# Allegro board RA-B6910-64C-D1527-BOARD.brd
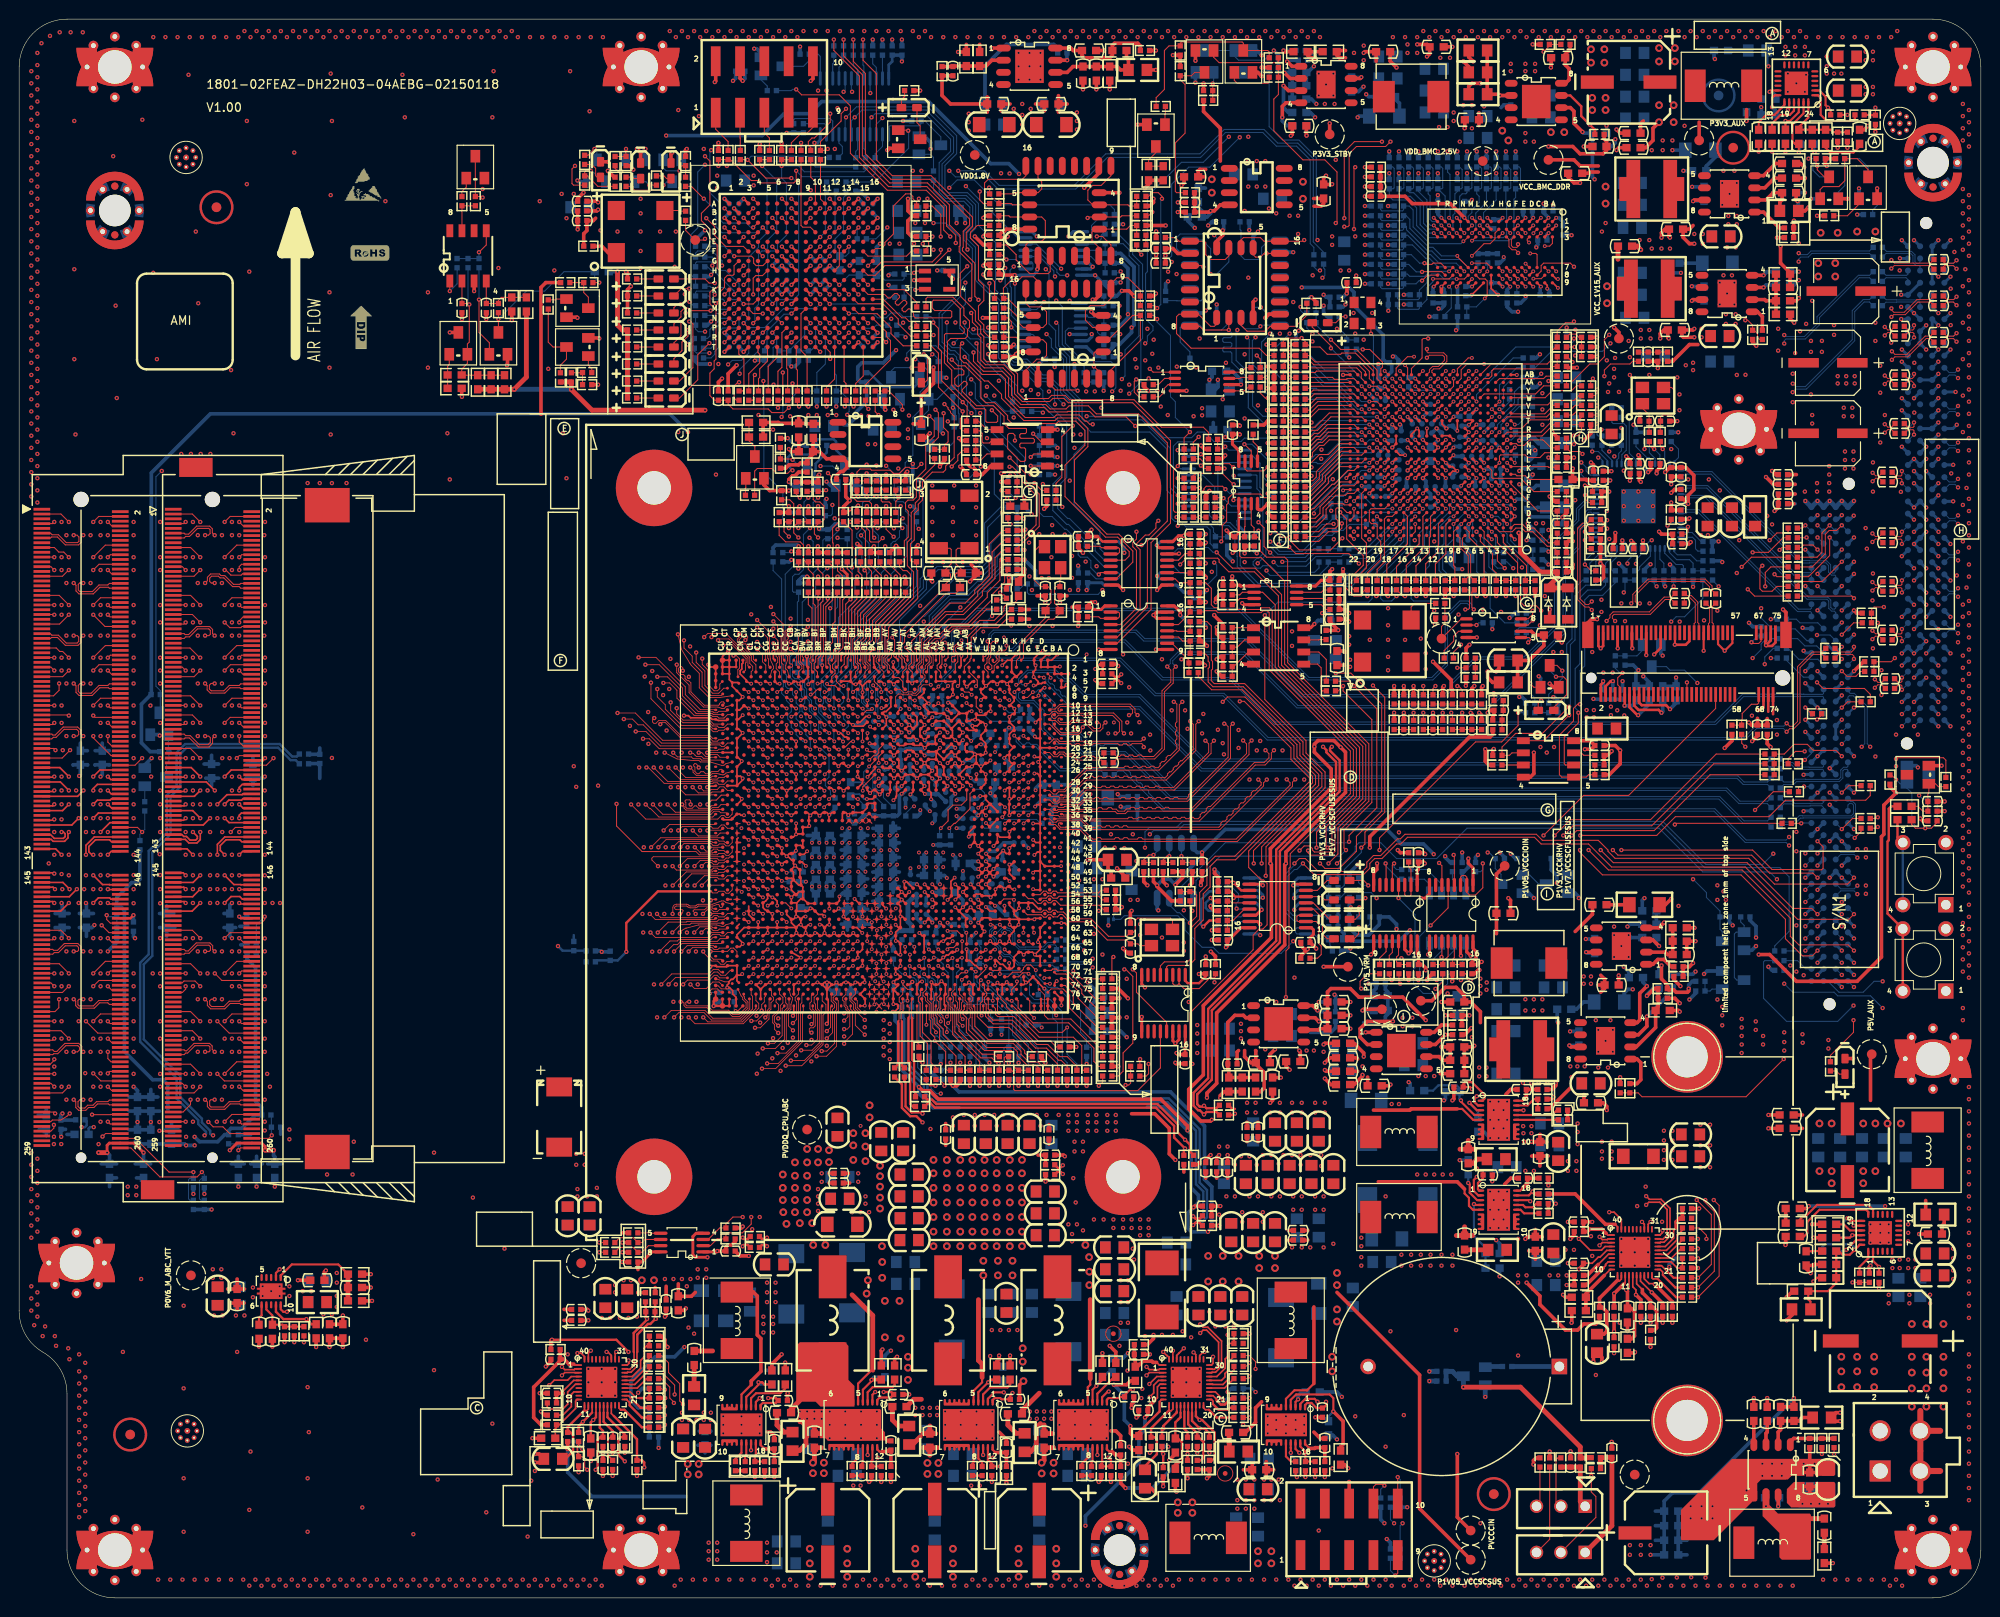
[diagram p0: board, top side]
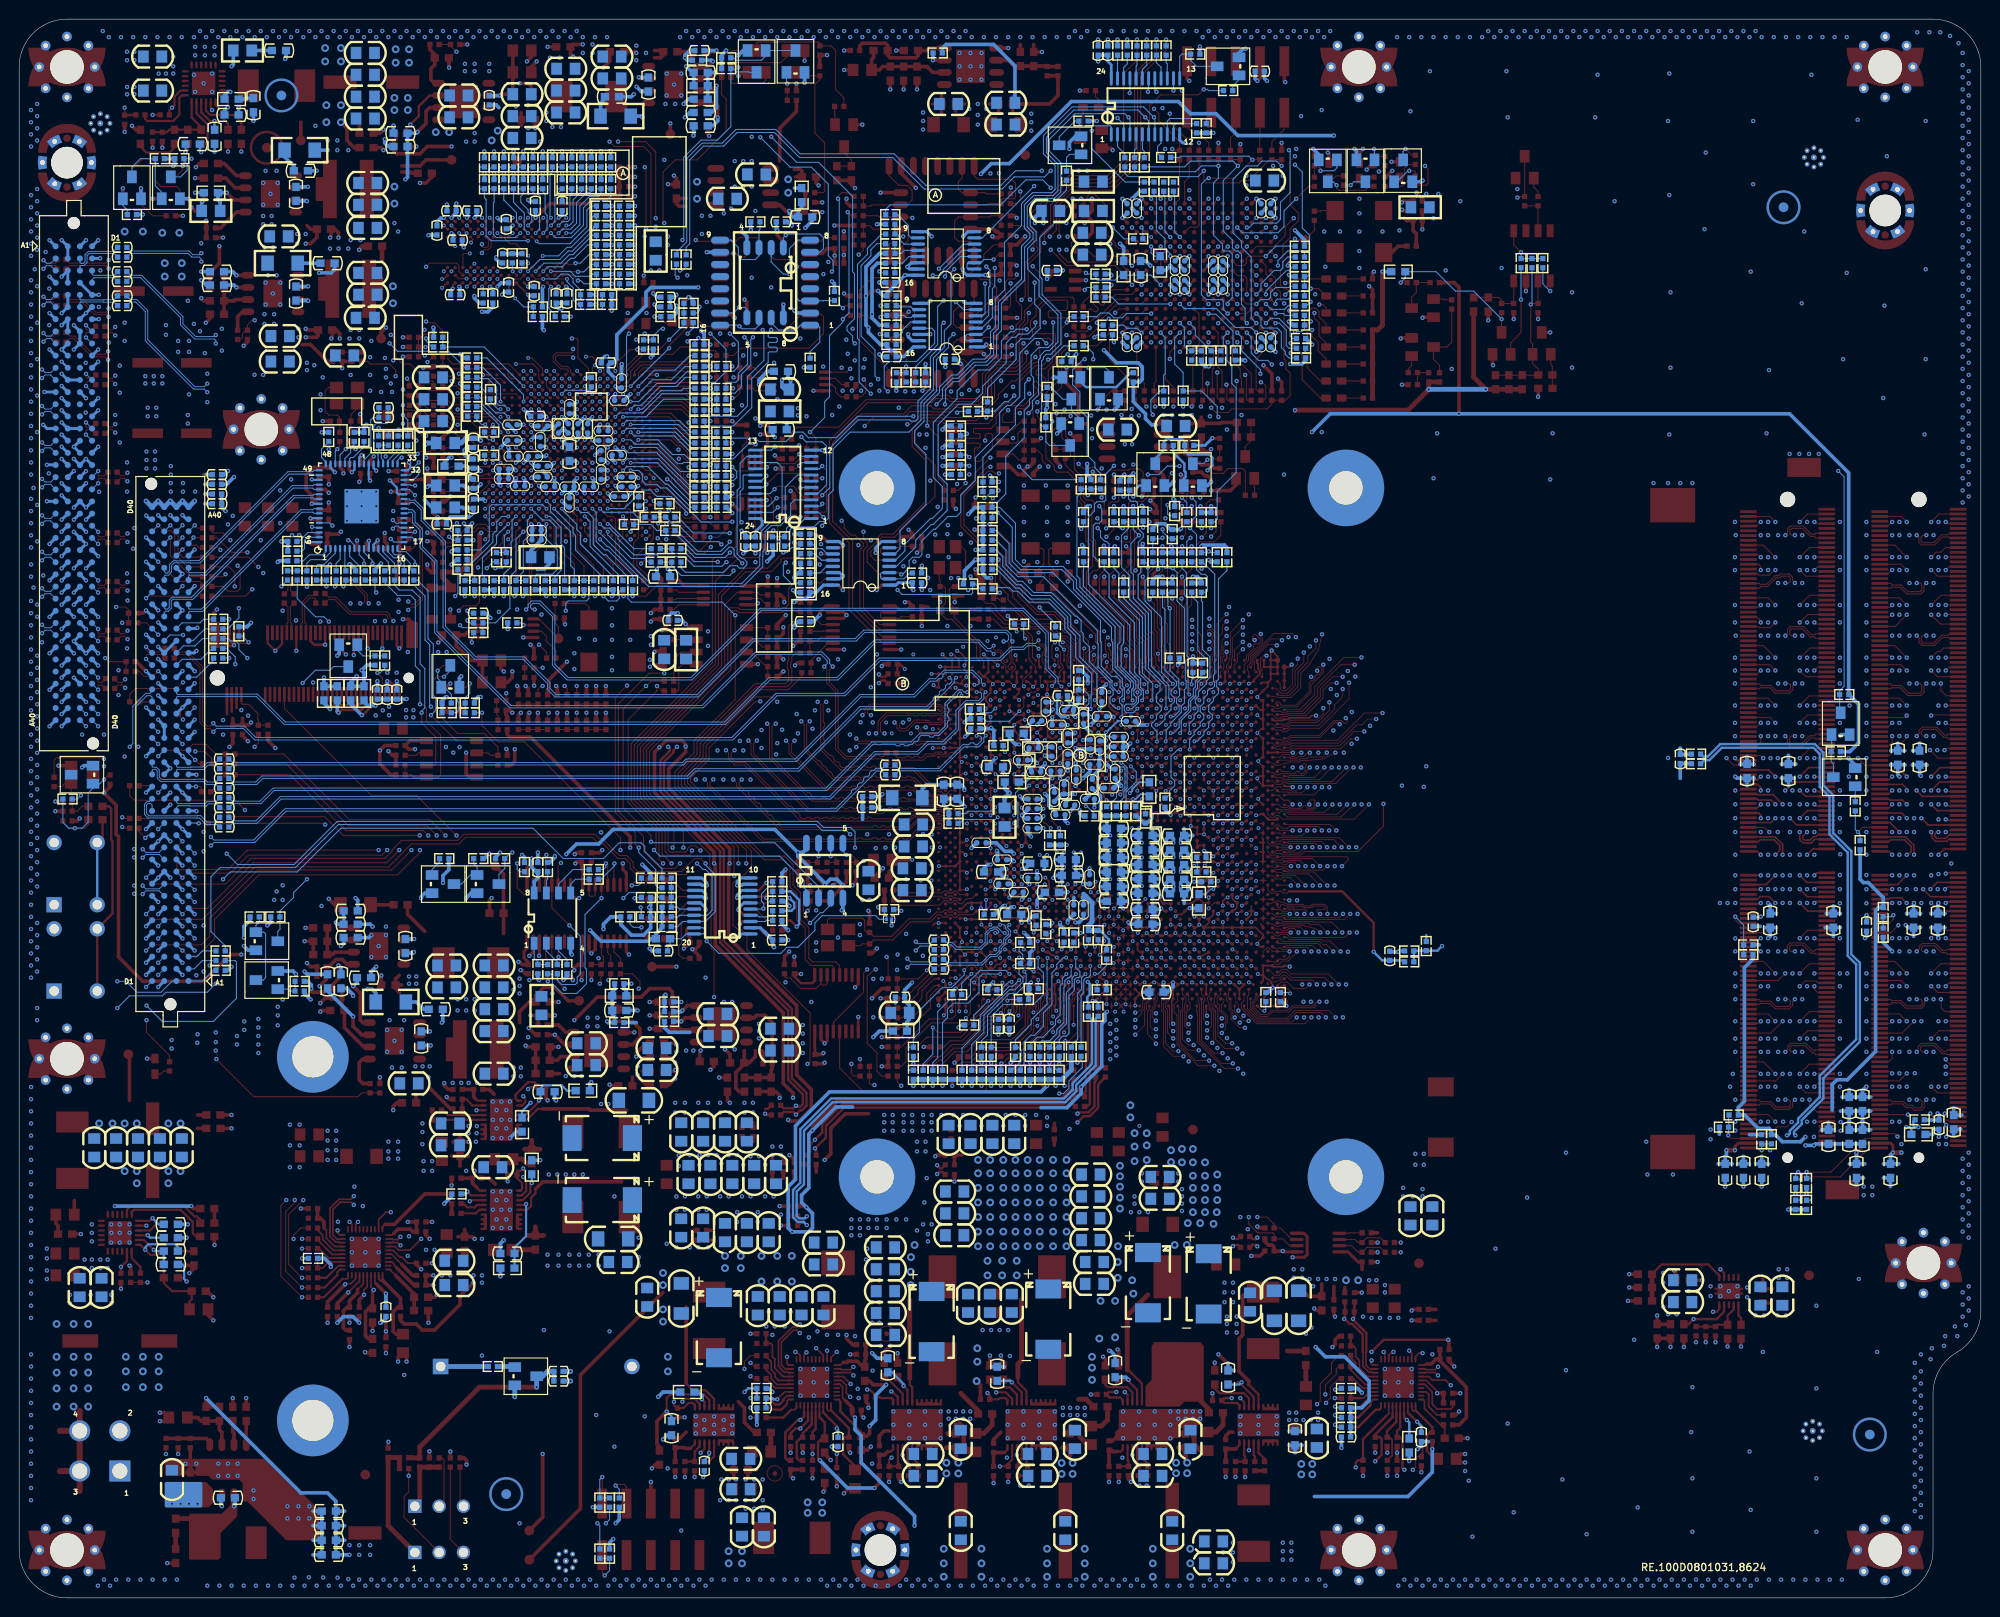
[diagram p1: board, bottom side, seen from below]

Outline 205 x 165 mm; copper layers: TOP, GND1, SIG1, GND2, SIG2, POWER1, POWER2, SIG3, GND3, SIG4, GND4, BOTTOM. Coordinates in mm from the lower left corner of the outline.
Outline path: 0,160 arc(1.46,163.54) 5,165 200,165 arc(203.54,163.54) 205,160 205,5 arc(203.54,1.46) 200,0 10,0 arc(6.46,1.46) 5,5 5,21.34 arc(4.33,23.84) 2.5,25.67 arc(0.67,27.5) 0,30 0,160

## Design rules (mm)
net group 24C02_WP: nets 24C02_WP N11777003
net group 1000M_MDI0: nets 1000M_MDI0N 1000M_MDI0P
net group 1000M_MDI1: nets 1000M_MDI1N 1000M_MDI1P
net group 1000M_MDI2: nets 1000M_MDI2N 1000M_MDI2P
net group 1000M_MDI3: nets 1000M_MDI3N 1000M_MDI3P
net group ADCAV33: nets N51572 N51617
net group ASKIP_VCCGBE: nets ASKIP_VCCGBE EN/FCCM_VCCSCSUS_16997268
net group ASKIP_VCCIN: nets ASKIP_VCCIN N16937550
net group ASKIP_VDDQ: nets ASKIP_VDDQ N17031638
net group BMC_9641_INT#: nets BMC_9641_INT# N12431544
net group BMC_ADC0: nets BMC_ADC0 N12560407
net group BMC_ADC1: nets BMC_ADC1 N12560503
net group BMC_ADC2: nets BMC_ADC2 N12560842
net group BMC_ADC3: nets BMC_ADC3 N12560934
net group BMC_ADC4: nets BMC_ADC4 N12558953
net group BMC_ADC5: nets BMC_ADC5 N12556062
net group BMC_ADC6: nets BMC_ADC6 N12556533
net group BMC_ADC7: nets BMC_ADC7 N12557485
net group BMC_ADC8: nets BMC_ADC8 N12558669
net group BMC_ADC9: nets BMC_ADC9 N12558773
net group BMC_ALERT_N: nets BMC_ALERT_N N187134720
net group BMC_EXTRST_N: nets BMC_EXTRST_N N18404132
net group BMC_GPIO_RS0: nets BMC_GPIO_RS0 N12446840
net group BMC_I2C_RST#: nets BMC_I2C_RST# N12451802
net group BMC_I2C_SCL: nets BMC_I2C_SCL N18655553
net group BMC_SCL: nets BMC_SCL N18713379
net group BMC_SDA: nets BMC_SDA N18713382
net group BMC_SRST_N: nets BMC_SRST_N N18404109
net group BMCO_UART_RXD1: nets BMC_UART_RXD1 BMCO_UART_RXD1
net group BMCO_UART_TXD1: nets BMC_UART_TXD1 BMCO_UART_TXD1
net group BROAD_RST#: nets BROAD_RST# N12446425
net group BSKIP_P1V05_PCH: nets BSKIP_P1V05_PCH EN/FCCM_P1V05_PCH
net group BSKIP_P2V5_VPP: nets BSKIP_P2V5_VPP EN/FCCM_VCCSCSUS_17116599
net group BSKIP_VCCSCSUS: nets BSKIP_VCCSCSUS EN/FCCM_VCCSCSUS
net group CATERR_N: nets CATERR_N CATERR_N_GTL
net group CIE_TX_0: nets PCIE_TX_N0 PCIE_TX_P0
net group CIE_TX_1: nets PCIE_TX_N1 PCIE_TX_P1
net group CIE_TX_2: nets PCIE_TX_N2 PCIE_TX_P2
net group CIE_TX_3: nets PCIE_TX_N3 PCIE_TX_P3
net group CLK_33M: nets CLK_33M N1731399
net group CLK_33M_LOOPBACK: nets CLK_33M_LOOPBACK N1731571
net group CLKOUT_CIE_D0: nets CLKOUT_PCIE_DN0 CLKOUT_PCIE_DP0
net group CLKOUT_CIE_D1: nets CLKOUT_PCIE_DN1 CLKOUT_PCIE_DP1
net group CLKOUT_CIE_D2: nets CLKOUT_PCIE_DN2 CLKOUT_PCIE_DP2
net group CLKOUT_CIE_D3: nets CLKOUT_PCIE_DN3 CLKOUT_PCIE_DP3
net group CLKOUT_CIE_D4: nets CLKOUT_PCIE_DN4 CLKOUT_PCIE_DP4
net group CLKOUT_CIE_D5: nets CLKOUT_PCIE_DN5 CLKOUT_PCIE_DP5
net group CLKOUT_CIE_D6: nets CLKOUT_PCIE_DN6 CLKOUT_PCIE_DP6
net group CLKOUT_CIE_D7: nets CLKOUT_PCIE_DN7 CLKOUT_PCIE_DP7
net group CPLD_25M_CLK: nets CPLD_25M_CLK N17832341
net group CPLD_CLK_50M: nets CPLD_CLK_50M N12564408
net group CPLD_ERR0_N: nets CPLD_ERR0_N N13331287
net group CPLD_ERR1_N: nets CPLD_ERR1_N N13331583
net group CPLD_ERR2_N: nets CPLD_ERR2_N N13331888
net group CPLD_M2_DEVSLP: nets CPLD_M2_DEVSLP N17107982
net group CPLD_MOLEX_UART_RXD0: nets CPLD_MOLEX_UART_RXD0 N12460724
net group CPLD_MOLEX_UART_TXD0: nets CPLD_MOLEX_UART_TXD0 N12457550
net group CPLD_SAVEN0: nets CPLD_SAVEN0 PUD_SAEN0
net group CPLD_SAVEN1: nets CPLD_SAVEN1 PUD_SAEN1
net group CPLD_SLP_S3_N: nets CPLD_SLP_S3_N SLP_S3_CPU_GTL
net group CPU_ERROR0_N: nets CPU_ERROR0_N CPU_ERROR0_N_GTL
net group CPU_ERROR1_N: nets CPU_ERROR1_N CPU_ERROR1_N_GTL
net group CPU_ERROR2_N: nets CPU_ERROR2_N CPU_ERROR2_N_GTL
net group CPU_MEMHOT: nets CPU_MEMHOT CPU_MEMHOT_GTL
net group CPU_PROCHOT: nets CPU_PROCHOT CPU_PROCHOT_GTL
net group CPU_THROTTLE: nets CPU_THROTTLE CPU_THROTTLE_GTL
net group DDR_SCL: nets DDR_SCL N13190679
net group DDR_SDA: nets DDR_SDA N13190675
net group DDR_VREF: nets DDR_VREF DDR_VREF_CPU
net group DIFF5: nets N1690001 N1690029
net group DIFF6: nets N1689961 N1689981
net group DIFF7: nets N1690117 N1690121
net group DIFF8: nets N1690065 N1690077
net group DIFFPAIR8: nets N16697962 N16697994
net group DIFFPAIR9: nets N16698122 N16698154
net group DIFFPAIR10: nets N16697668 N16697688
net group E1_RX_0: nets PE1_RX_N0 PE1_RX_P0
net group E1_RX_1: nets PE1_RX_N1 PE1_RX_P1
net group E1_RX_2: nets PE1_RX_N2 PE1_RX_P2
net group E1_RX_3: nets PE1_RX_N3 PE1_RX_P3
net group E1_RX_4: nets PE1_RX_N4 PE1_RX_P4
net group E1_RX_5: nets PE1_RX_N5 PE1_RX_P5
net group E1_RX_6: nets PE1_RX_N6 PE1_RX_P6
net group E1_RX_7: nets PE1_RX_N7 PE1_RX_P7
net group EN_P0V6_VTT: nets EN_P0V6_VTT N16755089
net group FP_PWR_LED: nets FP_PWR_LED N13419890
net group FWSPICS0#: nets FWSPICS0# FWSPICS0#_R
net group FWSPICS1#: nets FWSPICS1# FWSPICS1#_R
net group GPIO6_ONLINE_TMS: nets GPIO6_ONLINE_TMS N12431946
net group GPIO7_RS0: nets GPIO7_RS0 N12432021
net group GPIO15_CPU_9641_INT_N: nets GPIO15_CPU_9641_INT_N N12431744
net group GPIO28_MOD_PRE0: nets GPIO28_MOD_PRE0 N12451883
net group GPIO32_ONLINE_TDO: nets GPIO32_ONLINE_TDO N127846400
net group GPIO38_PCIE_CONFIG: nets GPIO38_PCIE_CONFIG N12446215
net group GPIO50_ONLINE_JTAG_EN: nets GPIO50_ONLINE_JTAG_EN N12432134
net group GPIO65_ONLINE_TCK: nets GPIO65_ONLINE_TCK N12494514
net group GPIO67_ONLINE_TDI: nets GPIO67_ONLINE_TDI N12494458
net group GPIO68_RS1: nets GPIO68_RS1 N12432061
net group GPIO71_I2C_RST_N: nets GPIO71_I2C_RST_N N12446036
net group GPIOZ3: nets GPIOZ3 N18581734
net group I210_REF_CLK: nets I210_REF_CLK N18446681
net group I210_XOUT: nets I210_XOUT N18446673
net group KR_0_TX_D: nets KR_P0_TX_DN KR_P0_TX_DP
net group KR_1_TX_D: nets KR_P1_TX_DN KR_P1_TX_DP
net group KR_P0_RX_DN: nets KR_P0_RX_DN N1709612
net group KR_P0_RX_DP: nets KR_P0_RX_DP N1709608
net group KR_P1_RX_DN: nets KR_P1_RX_DN N1709672
net group KR_P1_RX_DP: nets KR_P1_RX_DP N1709676
net group LAN_ALERT_N_GTL: nets LAN_ALERT_N_GTL N11710357
net group LAN_CLK: nets LAN_CLK LAN_SPI_CLK_GTL
net group LAN_CS: nets LAN_CS LAN_SPI_CS_GTL
net group LAN_DI: nets LAN_DI LAN_SPI_DI_GTL
net group LAN_DO: nets LAN_DO LAN_SPI_DO_GTL
net group LAN_PWRGD: nets LAN_PWRGD LAN_PWRGD_GTL
net group LAN_SCL_GTL: nets LAN_SCL_GTL N11710283
net group LAN_SDA_GTL: nets LAN_SDA_GTL N11710317
net group LAN_SPI_CLK: nets LAN_SPI_CLK N1710926
net group LAN_SPI_CS: nets LAN_SPI_CS N1710854
net group LAN_SPI_DI: nets LAN_SPI_DI N1710898
net group LAN_SPI_DO: nets LAN_SPI_DO N1710922
net group LED: nets LED N12580885
net group LED_HDD_ACTIVITY_N: nets LED_HDD_ACTIVITY_N N13334891
net group LM75_OS: nets LM75_OS N13421232
net group LPC_33M_BMC: nets LPC_33M_BMC N1731697
net group LPC_33M_CPLD: nets LPC_33M_CPLD N1731791
net group LPC_RST_N: nets LPC_RST_N N12494901
net group M_A_CLK_D1: nets M_A_CLK_DN1 M_A_CLK_DP1
net group M_A_CLK_D3: nets M_A_CLK_DN3 M_A_CLK_DP3
net group M_A_DQS_D9: nets M_A_DQS_DN9 M_A_DQS_DP9
net group M_A_DQS_D10: nets M_A_DQS_DN10 M_A_DQS_DP10
net group M_A_DQS_D11: nets M_A_DQS_DN11 M_A_DQS_DP11
net group M_A_DQS_D12: nets M_A_DQS_DN12 M_A_DQS_DP12
net group M_A_DQS_D13: nets M_A_DQS_DN13 M_A_DQS_DP13
net group M_A_DQS_D14: nets M_A_DQS_DN14 M_A_DQS_DP14
net group M_A_DQS_D15: nets M_A_DQS_DN15 M_A_DQS_DP15
net group M_A_DQS_D16: nets M_A_DQS_DN16 M_A_DQS_DP16
net group M_A_DQS_D17: nets M_A_DQS_DN17 M_A_DQS_DP17
net group M_B_CLK_D1: nets M_B_CLK_DN1 M_B_CLK_DP1
net group M_B_CLK_D3: nets M_B_CLK_DN3 M_B_CLK_DP3
net group M_B_DQS_D9: nets M_B_DQS_DN9 M_B_DQS_DP9
net group M_B_DQS_D10: nets M_B_DQS_DN10 M_B_DQS_DP10
net group M_B_DQS_D11: nets M_B_DQS_DN11 M_B_DQS_DP11
net group M_B_DQS_D12: nets M_B_DQS_DN12 M_B_DQS_DP12
net group M_B_DQS_D13: nets M_B_DQS_DN13 M_B_DQS_DP13
net group M_B_DQS_D14: nets M_B_DQS_DN14 M_B_DQS_DP14
net group M_B_DQS_D15: nets M_B_DQS_DN15 M_B_DQS_DP15
net group M_B_DQS_D16: nets M_B_DQS_DN16 M_B_DQS_DP16
net group M_B_DQS_D17: nets M_B_DQS_DN17 M_B_DQS_DP17
net group M_CPU0_EVENT_N: nets M_CPU0_EVENT_N N18373532
net group N12395045: nets N12395045 N12395788
net group N12395875: nets N12395875 N12395879
net group N12402803: nets N12402803 N12402827
net group N12402927: nets N12402927 N12402999
net group N12580929: nets N12580929 N12580933
net group N13252429: nets N13252429 N13252463
net group N13331331: nets N13331331 N13331335
net group N13331627: nets N13331627 N13331631
net group N13331932: nets N13331932 N13331936
net group N13479725: nets N13479725 N16975982
net group N17832270: nets N17832270 N17832309
net group N18446289: nets N18446289 N18446291
net group N125223760: nets N12522400 N125223760
net group NCSI_NIC_ACT: nets N12432641 NCSI_NIC_ACT
net group NCSI_NIC_LED_100M: nets N12457439 NCSI_NIC_LED_100M
net group NCSI_NIC_LED_1000M: nets N12457473 NCSI_NIC_LED_1000M
net group NIC_FLASH_CE_N: nets N1841534014 NIC_FLASH_CE_N
net group NIC_FLASH_SCK: nets N1841534012 NIC_FLASH_SCK
net group NIC_FLASH_SI: nets N1841534011 NIC_FLASH_SI
net group NIC_FLASH_SO: nets N1841534013 NIC_FLASH_SO
net group ONLINE_CPLD_JTAG_EN: nets N14342396 ONLINE_CPLD_JTAG_EN
net group ONLINE_TCK: nets N1756293914 ONLINE_TCK
net group ONLINE_TDI: nets N1756293919 ONLINE_TDI
net group ONLINE_TDO: nets N1756293915 ONLINE_TDO
net group ONLINE_TMS: nets N1756293918 ONLINE_TMS
net group OSC_50M: nets N12565688 OSC_50M
net group P1V2_VDDQ_PG: nets N16706105 P1V2_VDDQ_PG
net group P1V3_VCCKRHV_EN: nets N12409933 P1V3_VCCKRHV_EN
net group P1V05_PCH_EN: nets N17040089 P1V05_PCH_EN
net group P1V05_PCH_PG: nets N16706101 P1V05_PCH_PG
net group P1V05_PROC_IO_EN: nets N12402879 P1V05_PROC_IO_EN
net group P1V05_VCCCIOIN_EN: nets N13485589 P1V05_VCCCIOIN_EN
net group P1V5_VRM_EN: nets N12417603 P1V5_VRM_EN
net group P1V7_VCCSCFUSESUS_EN: nets N1789520 P1V7_VCCSCFUSESUS_EN
net group P2V5_VPP_EN: nets N17047812 P2V5_VPP_EN
net group P2V5_VPP_PG: nets N16706132 P2V5_VPP_PG
net group P3V3_AUX_EN: nets N12523074 P3V3_AUX_EN
net group P3V3_EN: nets N12394792 P3V3_EN
net group P5V_AUX_EN: nets N13474526 P5V_AUX_EN
net group PCH_WAKE_N: nets N12467054 PCH_WAKE_N
net group PCHHOT_CPU_N: nets PCHHOT_CPU_N PCHHOT_CPU_N_GTL
net group PE1_TX_N0: nets N14075081 PE1_TX_N0
net group PE1_TX_N1: nets N14075001 PE1_TX_N1
net group PE1_TX_N2: nets N14075019 PE1_TX_N2
net group PE1_TX_N3: nets N14074975 PE1_TX_N3
net group PE1_TX_N4: nets N14074993 PE1_TX_N4
net group PE1_TX_N5: nets N14075011 PE1_TX_N5
net group PE1_TX_N6: nets N14074967 PE1_TX_N6
net group PE1_TX_N7: nets N14074985 PE1_TX_N7
net group PE1_TX_P0: nets N14075085 PE1_TX_P0
net group PE1_TX_P1: nets N14074977 PE1_TX_P1
net group PE1_TX_P2: nets N14074995 PE1_TX_P2
net group PE1_TX_P3: nets N14075013 PE1_TX_P3
net group PE1_TX_P4: nets N14074969 PE1_TX_P4
net group PE1_TX_P5: nets N14074987 PE1_TX_P5
net group PE1_TX_P6: nets N14075005 PE1_TX_P6
net group PE1_TX_P7: nets N14074963 PE1_TX_P7
net group PE2_RX_N0: nets N18484631 PE2_RX_N0
net group PE2_RX_P0: nets N18484629 PE2_RX_P0
net group PE2_TX_N0: nets N1702143 PE2_TX_N0
net group PE2_TX_P0: nets N1702147 PE2_TX_P0
net group PERST_M.2_N: nets N12515607 PERST_M.2_N
net group PIRQA_N: nets N12446074 PIRQA_N
net group PROCPWRGD_PCH: nets PROCPWRGD_PCH PROCPWRGD_PCH_GTL
net group PWRGD_CPU: nets PWRGD_CPU PWRGD_CPU_GTL
net group PWRGD_PS_PWROK: nets N18601328 PWRGD_PS_PWROK
net group RESET_CPU_N: nets RESET_CPU_N RESET_CPU_N_GTL
net group RMII1CRSDV: nets N184153402 RMII1CRSDV
net group RMII1RXD0: nets N184153405 RMII1RXD0
net group RMII1RXD1: nets N184153404 RMII1RXD1
net group RMII1TXD0: nets RMII1TXD0 RMII1TXD0_R
net group RMII1TXD1: nets RMII1TXD1 RMII1TXD1_R
net group RMII1TXEN: nets RMII1TXEN RMII1TXEN_R
net group RSMRST_CPU_N: nets RSMRST_CPU_N RSMRST_CPU_N_GTL
net group SATA_RX_D0: nets SATA_RX_DN0 SATA_RX_DP0
net group SATA_RX_D5: nets SATA_RX_DN5 SATA_RX_DP5
net group SATA_RX_DN1: nets N17105459 SATA_RX_DN1
net group SATA_RX_DN2: nets N17794996 SATA_RX_DN2
net group SATA_RX_DN3: nets N17794486 SATA_RX_DN3
net group SATA_RX_DN4: nets N17794271 SATA_RX_DN4
net group SATA_RX_DP1: nets N17105456 SATA_RX_DP1
net group SATA_RX_DP2: nets N17794993 SATA_RX_DP2
net group SATA_RX_DP3: nets N17794489 SATA_RX_DP3
net group SATA_RX_DP4: nets N17794274 SATA_RX_DP4
net group SATA_TX_D0: nets SATA_TX_DN0 SATA_TX_DP0
net group SATA_TX_D5: nets SATA_TX_DN5 SATA_TX_DP5
net group SATA_TX_DN1: nets N17105487 SATA_TX_DN1
net group SATA_TX_DN2: nets N17795581 SATA_TX_DN2
net group SATA_TX_DN3: nets N17750784 SATA_TX_DN3
net group SATA_TX_DN4: nets N17756089 SATA_TX_DN4
net group SATA_TX_DP1: nets N17105490 SATA_TX_DP1
net group SATA_TX_DP2: nets N17795291 SATA_TX_DP2
net group SATA_TX_DP3: nets N17750781 SATA_TX_DP3
net group SATA_TX_DP4: nets N17756086 SATA_TX_DP4
net group SERIRQ_DATA: nets N11794527 SERIRQ_DATA
net group SML1_CLK: nets N18490497 SML1_CLK
net group SML1_DATA: nets N18490477 SML1_DATA
net group SMLINK0_ALERT_N: nets N12495930 SMLINK0_ALERT_N
net group SPI_BMC_EN: nets N17481397 SPI_BMC_EN
net group SPI_BMC_OE: nets N17482004 SPI_BMC_OE
net group SPI_CPU_OE: nets N17481458 SPI_CPU_OE
net group SPKR_CPLD: nets N16903915 SPKR_CPLD
net group SRTCRST_N: nets N13251979 SRTCRST_N
net group SVID_CLK: nets N1730709 SVID_CLK
net group SYS_UART_CTS1: nets N18565933 SYS_UART_CTS1
net group SYS_UART_DCD1: nets N18565936 SYS_UART_DCD1
net group SYS_UART_DSR1: nets N18565939 SYS_UART_DSR1
net group SYS_UART_DTR1: nets N18565945 SYS_UART_DTR1
net group SYS_UART_RI1: nets N18565942 SYS_UART_RI1
net group SYS_UART_RTS1: nets N18565948 SYS_UART_RTS1
net group THERMTRIP_CPU_N: nets THERMTRIP_CPU_N THERMTRIP_CPU_N_GTL
net group TO_BMC_INT#: nets N12446773 TO_BMC_INT#
net group TPS3823_MR_N: nets N12435911 TPS3823_MR_N
net group UART_RX0: nets UART_RX0 UART_RX0_GTL
net group UART_TX0: nets UART_TX0 UART_TX0_GTL
net group USB2_D1: nets USB2_DN1 USB2_DP1
net group USB2_D2: nets USB2_DN2 USB2_DP2
net group USB2_DN0: nets N12451452 USB2_DN0
net group USB2_DP0: nets N12451530 USB2_DP0
net group USB2A_DN: nets USB2_DN3 USB2A_DN
net group USB2A_DP: nets USB2_DP3 USB2A_DP
net group USB3_RX_D1: nets USB3_RX_DN1 USB3_RX_DP1
net group USB3_TX_DN1: nets N1713630 USB3_TX_DN1
net group USB3_TX_DP1: nets N1713626 USB3_TX_DP1
net group USB_OC0: nets N12494701 USB_OC0
net group VCC_1V15_AUX_EN: nets N1774764 VCC_1V15_AUX_EN
net group VCC_BMC_DDR_EN: nets N1767201 VCC_BMC_DDR_EN
net group VCCGBE_PG: nets N16706091 VCCGBE_PG
net group VCCGBE_SENSE: nets N16698318 VCCGBE_SENSE
net group VCCIN_SENSE: nets N16698676 VCCIN_SENSE
net group VCCSCSUS_EN: nets N17053094 VCCSCSUS_EN
net group VCCSCSUS_SENSE: nets N16698500 VCCSCSUS_SENSE
net group VDD_BMC_2.5V_EN: nets N12424653 VDD_BMC_2.5V_EN
net group VR_FAULT: nets VR_FAULT VR_FAULT_VCCIN_VCCSCSUS
net group VR_FAULT_17088173: nets VR_FAULT_17088173 VR_FAULT_VDDQ
net group VR_FAULT_17093326: nets VR_FAULT_17093326 VR_FAULT_VCCGBE_P1V05_PCH
net group VR_HOT_VCCGBE_P1V05_PCH: nets N16705352 VR_HOT_VCCGBE_P1V05_PCH
net group VR_HOT_VCCIN_VCCSCSUS: nets N16705316 VR_HOT_VCCIN_VCCSCSUS
net group VR_HOT_VDDQ: nets N16705397 VR_HOT_VDDQ
net group VREF_P_VCCGBE_P1V05_PCH: nets VREF_P_VCCGBE_P1V05_PCH VREF_VCCGBE_P1V05_PCH
net group VREF_P_VCCIN_VCCSCSUS: nets VREF_P_VCCIN_VCCSCSUS VREF_VCCIN_VCCSCSUS
net group VREF_P_VDDQ_P2V5_VPP: nets VREF_P_VDDQ_P2V5_VPP VREF_VDDQ_P2V5_VPP
net group VSS_VCCGBE_SENSE: nets N16698306 VSS_VCCGBE_SENSE
net group VSS_VCCIN_SENSE: nets N16698648 VSS_VCCIN_SENSE
net group VSS_VCCSCSUS_SENSE: nets N16698468 VSS_VCCSCSUS_SENSE
net group 12V_VCCGBE_P1V05_PCH: nets N17039294
net group 12V_VCCIN_VCCSCSUS: nets N17052448
net group 12V_VDDQ_P2V5_VPP: nets N17047383
net group AC: nets ACSP1_VCCGBE ACSP1_VCCIN ACSP1_VDDQ ACSP2_VCCIN BCSP1_P1V05_PCH BCSP1_P2V5_VPP BCSP1_VCCSCSUS
net group BMC_I2C_SDA: nets BMC_I2C_SDA N12451741 N18655556
net group BMC_READY_N: nets BMC_READY_N N12494143 N18673994
net group BMC_RMII_CLK: nets BMC_RMII_CLK BMC_RMII_CLK_50M N12564244 N12564264 NIC0_RMII_RXCLK NIC0_RMII_RXCLK_50M RMII1RCLKO_BMC
net group BMC_RSTBTN_R: nets BMC_RSTBTN_R N12546465 RST_BTN_PASS_N
net group BROAD_12V_EN: nets BROAD_12V_EN N12451653 N12462137 N18601236
net group CLK: nets CLK N16975903 N16975906 SPI_CLK_0 SPI_CLK_1
net group CON_33M_CLK: nets CON_33M_CLK N1731591 N1743791
net group CPLD_CSN0: nets CPLD_CSN0 CSN0 SPI_CS_N_0
net group CPLD_CSN1: nets CPLD_CSN1 CSN1 SPI_CS_N_1
net group FP_PWR_BTN_R: nets FP_PWR_BTN_R N12528497 PWR_BTN_PASS_N
net group FWSPICK: nets FWSPICK FWSPICK_R FWSPICKS
net group FWSPIMISO: nets FWSPIMISO FWSPIMISO_R FWSPIMISOS
net group FWSPIMOSI: nets FWSPIMOSI FWSPIMOSI_R FWSPIMOSIS
net group GPIO1_CPU_SCL: nets GPIO1_CPU_SCL N1747980 N11776877 N12431888 N12451021 N12459393 N12495914 N18657896 SMB_CPU_SCL SMLINK0_CLK
net group GPIO17_CPU_SDA: nets GPIO17_CPU_SDA N1747948 N11776881 N12431851 N12446006 N12459341 N12495922 N18657899 SMB_CPU_SDA SMLINK0_DATA
net group GPIO62: nets GPIO62 N12494253 SUSCLK_CPLD SUSCLK_M2
net group LAN_P0_ACTIVE_GTL: nets LAN_P0_ACTIVE_GTL N1771492 N13350706
net group LAN_P0_SPEED_GTL: nets LAN_P0_SPEED_GTL N1771500 N13350702
net group LPC_DA0: nets LPC_DA0 N1743888 N12456807 N18362458
net group LPC_DA1: nets LPC_DA1 N1743955 N12456811 N18362461
net group LPC_DA2: nets LPC_DA2 N1744023 N12456815 N18362464
net group LPC_DA3: nets LPC_DA3 N1744091 N12456949 N18362467
net group LPC_FRAME_N: nets LPC_FRAME_N N1743737 N12456803 N12494835
net group LPC_SERIRQ: nets LPC_SERIRQ N11795538 N12431813 N12727425 N13467875 SERIRQ SERIRQ_BMC
net group M_A_ADD: nets M_A_BA0 M_A_BA1 M_A_BG0 M_A_BG1 M_A_CKE0 M_A_CKE1 M_A_CS_N0 M_A_CS_N1 M_A_MA0 M_A_MA1 M_A_MA2 M_A_MA3 M_A_MA4 M_A_MA5 M_A_MA6 M_A_MA7 M_A_MA8 M_A_MA9 M_A_MA10 M_A_MA11 M_A_MA12 M_A_MA13 M_A_MA14 M_A_MA15 M_A_MA16 M_A_ODT0 M_A_ODT1 M_A_PAR M_ACT_N M_ALERT_N
net group M_A_CLK: nets M_A-CLK_DN2 M_A_CLK_DN0 M_A_CLK_DP0 M_A_CLK_DP2
net group M_A_DATA0: nets M_A_DQ0 M_A_DQ1 M_A_DQ2 M_A_DQ3 M_A_DQ4 M_A_DQ5 M_A_DQ6 M_A_DQ7 M_A_DQS_DN0 M_A_DQS_DP0
net group M_A_DATA1: nets M_A_DQ8 M_A_DQ9 M_A_DQ10 M_A_DQ11 M_A_DQ12 M_A_DQ13 M_A_DQ14 M_A_DQ15 M_A_DQS_DN1 M_A_DQS_DP1
net group M_A_DATA2: nets M_A_DQ16 M_A_DQ17 M_A_DQ18 M_A_DQ19 M_A_DQ20 M_A_DQ21 M_A_DQ22 M_A_DQ23 M_A_DQS_DN2 M_A_DQS_DP2
net group M_A_DATA3: nets M_A_DQ24 M_A_DQ25 M_A_DQ26 M_A_DQ27 M_A_DQ28 M_A_DQ29 M_A_DQ30 M_A_DQ31 M_A_DQS_DN3 M_A_DQS_DP3
net group M_A_DATA4: nets M_A_DQ32 M_A_DQ33 M_A_DQ34 M_A_DQ35 M_A_DQ36 M_A_DQ37 M_A_DQ38 M_A_DQ39 M_A_DQS_DN4 M_A_DQS_DP4
net group M_A_DATA5: nets M_A_DQ40 M_A_DQ41 M_A_DQ42 M_A_DQ43 M_A_DQ44 M_A_DQ45 M_A_DQ46 M_A_DQ47 M_A_DQS_DN5 M_A_DQS_DP5
net group M_A_DATA6: nets M_A_DQ48 M_A_DQ49 M_A_DQ50 M_A_DQ51 M_A_DQ52 M_A_DQ53 M_A_DQ54 M_A_DQ55 M_A_DQS_DN6 M_A_DQS_DP6
net group M_A_DATA7: nets M_A_DQ56 M_A_DQ57 M_A_DQ58 M_A_DQ59 M_A_DQ60 M_A_DQ61 M_A_DQ62 M_A_DQ63 M_A_DQS_DN7 M_A_DQS_DP7
net group M_A_DATA8: nets M_A_DQS_DN8 M_A_DQS_DP8 M_A_ECC0 M_A_ECC1 M_A_ECC2 M_A_ECC3 M_A_ECC4 M_A_ECC5 M_A_ECC6 M_A_ECC7
net group M_B_ADD: nets M_B_ACT_N M_B_ALERT_N M_B_BA0 M_B_BA1 M_B_BG0 M_B_BG1 M_B_CKE0 M_B_CKE1 M_B_CS_N0 M_B_CS_N1 M_B_MA0 M_B_MA1 M_B_MA2 M_B_MA3 M_B_MA4 M_B_MA5 M_B_MA6 M_B_MA7 M_B_MA8 M_B_MA9 M_B_MA10 M_B_MA11 M_B_MA12 M_B_MA13 M_B_MA14 M_B_MA15 M_B_MA16 M_B_ODT0 M_B_ODT1 M_B_PAR
net group M_B_CLK: nets M_B_CLK_DN0 M_B_CLK_DN2 M_B_CLK_DP0 M_B_CLK_DP2
net group M_B_DATA0: nets M_B_DQ0 M_B_DQ1 M_B_DQ2 M_B_DQ3 M_B_DQ4 M_B_DQ5 M_B_DQ6 M_B_DQ7 M_B_DQS_DN0 M_B_DQS_DP0
net group M_B_DATA1: nets M_B_DQ8 M_B_DQ9 M_B_DQ10 M_B_DQ11 M_B_DQ12 M_B_DQ13 M_B_DQ14 M_B_DQ15 M_B_DQS_DN1 M_B_DQS_DP1
net group M_B_DATA2: nets M_B_DQ16 M_B_DQ17 M_B_DQ18 M_B_DQ19 M_B_DQ20 M_B_DQ21 M_B_DQ22 M_B_DQ23 M_B_DQS_DN2 M_B_DQS_DP2
net group M_B_DATA3: nets M_B_DQ24 M_B_DQ25 M_B_DQ26 M_B_DQ27 M_B_DQ28 M_B_DQ29 M_B_DQ30 M_B_DQ31 M_B_DQS_DN3 M_B_DQS_DP3
net group M_B_DATA4: nets M_B_DQ32 M_B_DQ33 M_B_DQ34 M_B_DQ35 M_B_DQ36 M_B_DQ37 M_B_DQ38 M_B_DQ39 M_B_DQS_DN4 M_B_DQS_DP4
net group M_B_DATA5: nets M_B_DQ40 M_B_DQ41 M_B_DQ42 M_B_DQ43 M_B_DQ44 M_B_DQ45 M_B_DQ46 M_B_DQ47 M_B_DQS_DN5 M_B_DQS_DP5
net group M_B_DATA6: nets M_B_DQ48 M_B_DQ49 M_B_DQ50 M_B_DQ51 M_B_DQ52 M_B_DQ53 M_B_DQ54 M_B_DQ55 M_B_DQS_DN6 M_B_DQS_DP6
net group M_B_DATA7: nets M_B_DQ56 M_B_DQ57 M_B_DQ58 M_B_DQ59 M_B_DQ60 M_B_DQ61 M_B_DQ62 M_B_DQ63 M_B_DQS_DN7 M_B_DQS_DP7
net group M_B_DATA8: nets M_B_DQS_DN8 M_B_DQS_DP8 M_B_ECC0 M_B_ECC1 M_B_ECC2 M_B_ECC3 M_B_ECC4 M_B_ECC5 M_B_ECC6 M_B_ECC7
net group MISO: nets MISO N16975938 N16975941 SPI_MISO_0 SPI_MISO_1
net group MOSI: nets MOSI N16975861 N16975864 SPI_MOSI_0 SPI_MOSI_1
net group N1766937: nets N1766937
net group N1774506: nets N1774506
net group N1789254: nets N1789254
net group N13473942: nets N13473942 N13473946 N13473950 N13474144
net group N13474364: nets N13474368 N13474606 N13474690
net group N13478611: nets N13478611
net group N13485295: nets N13485597
net group N16794342: nets N16794342 N16794347 N16794368
net group N16997274: nets N16997274 N16997276 N16997279
net group N16998858: nets N16998858 N16998860 N16998866
net group N17031650: nets N17031650 N17031652 N17031694
net group N17116587: nets N17116587 N17116589 N17116595
net group N125223401: nets N12522444 N12522448 N12522508 N125223401
net group N169417421: nets N16941751 N16941772 N169417421
net group N169486101: nets N16948700 N16948702 N169486101
net group P1V05_PROC_IO: nets N13450164 P1V05_PROC_IO THERMTRIP_PCH_N THERMTRIP_PCH_N_GTL
net group P1V7_VCCSCFUSESUS: nets N1789730
net group PCIE: nets PCIE_RX_N0 PCIE_RX_N1 PCIE_RX_N2 PCIE_RX_N3 PCIE_RX_P0 PCIE_RX_P1 PCIE_RX_P2 PCIE_RX_P3
net group PECI_BMC: nets N1730757 N18491459 PECI_BMC
net group PMB_ALERT: nets PMB_ALERT PMB_ALERT_VCCGBE_P1V05_PCH PMB_ALERT_VCCIN_VCCSCSUS PMB_ALERT_VDDQ
net group PMB_CLK: nets N18657207 PMB_CLK PMB_CLK_VCCGBE_P1V05_PCH PMB_CLK_VCCIN_VCCSCSUS PMB_CLK_VDDQ VR_PMCLK
net group PMB_DIO: nets N18657210 PMB_DIO PMB_DIO_VCCGBE_P1V05_PCH PMB_DIO_VCCIN_VCCSCSUS PMB_DIO_VDDQ VR_PMDATA
net group PWM: nets APWM1_VCCGBE APWM1_VCCIN APWM1_VDDQ BPWM1_P1V05_PCH BPWM1_P2V5_VPP BPWM1_VCCSCSUS
net group PWR_BTN_N: nets N12526853 N12527562 N18603109 PWR_BTN_N
net group RST_BTN_N: nets N12527267 N12541458 N18603113 RST_BTN_N
net group SALERT_VCCGBE_P1V05_PCH: nets SALERT_VCCGBE_P1V05_PCH SALERT_VCCIN_VCCSCSUS SALERT_VDDQ SVID_ALERT_N
net group SDIO_VCCGBE_P1V05_PCH: nets N1730669 SDIO_VCCGBE_P1V05_PCH SDIO_VCCIN_VCCSCSUS SDIO_VDDQ SVID_DATA
net group SMB_SENSOR_CLK: nets N12569009 N18657671 SMB_SENSOR_CLK
net group SMB_SENSOR_DATA: nets N12569029 N18657674 SMB_SENSOR_DATA
net group SML1ALERT_N: nets N12727421 N18673991 SML1ALERT_N
net group SPI_CS_CPLD: nets N17480014 N17480023 SPI_CS_CPLD
net group SPI_HOLD_N_0: nets SPI_HOLD_N_0 SPI_HOLD_N_1 SPI_IO3
net group SPI_IO2: nets SPI_IO2 SPI_WP_N_0 SPI_WP_N_1
net group SPI_SSB_BMC_CLK: nets SPI_SSB_BMC_CLK SPI_SSB_CLK SPI_SSB_F_CLK
net group SPI_SSB_BMC_MISO: nets SPI_SSB_BMC_MISO SPI_SSB_F_MISO SPI_SSB_MISO
net group SPI_SSB_BMC_MOSI: nets SPI_SSB_BMC_MOSI SPI_SSB_F_MOSI SPI_SSB_MOSI
net group SPI_SSB_CS0_BMC_N: nets SPI_SSB_CS0_BMC_N SPI_SSB_CS0_CPLD_N SPI_SSB_CS0_N
net group TAO_VCCGBE_P1V05_PCH: nets N16997281 N16998909 TAO_VCCGBE_P1V05_PCH
net group TAO_VCCIN_VCCSCSUS: nets N16794661 N16941889 N16948718 TAO_VCCIN_VCCSCSUS
net group TAO_VDD_P2V5_VPP: nets N17031655 N17116638 TAO_VDD_P2V5_VPP
net group TCK: nets N12441283 N17563236 TCK
net group TDI: nets N12441326 N17563239 TDI
net group TDO: nets N12441300 N17563245 TDO
net group TMS: nets N12441304 N17563242 TMS
net group VCCIN_PG: nets N16706083 N18601239 VCCIN_PG
net group VCCSCSUS_PG: nets N16706087 N16909700 VCCSCSUS_PG
net group VDD_BMC_2.5V: nets N12425131

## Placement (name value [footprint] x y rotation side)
BZ1  AAA_BAT_029_K01  [BATTERY]  160.96 24.18 180 top
C1  105  [C0402]  199.94 81.2 180 top
C2  105  [C0402]  199.94 83.24 0 top
C3  104  [C0402]  144.7 91.24 270 top
C4  104  [C0402]  154.61 92.76 0 top
C5  104  [C0402]  147.75 91.24 270 top
C6  104  [C0402]  151.68 98.22 0 top
C7  104  [C0402]  151.81 93.9 270 top
C8  104  [C0402]  151.81 91.24 270 top
C9  104  [C0402]  145.72 93.9 270 top
C10  104  [C0402]  163.75 130.73 180 top
C11  104  [C0402]  170.23 129.72 90 top
C12  104  [C0402]  148.76 93.9 270 top
C13  4.7P  [C0402]  157.02 102.92 180 bottom
C14  104  [C0603]  137.71 106.73 180 bottom
C15  106  [C0805]  137.59 99.11 270 bottom
C16  104  [C0603]  137.71 98.22 270 top
C17  X  [C0402]  148.51 102.41 180 top
C18  104  [C0603]  133.78 153.85 180 top
C19  106  [C0805]  155.62 97.97 180 top
C20  104  [C0603]  160.07 100.64 180 top
C21  104  [C0402]  137.46 102.29 180 top
C22  104  [C0402]  83.21 137.24 270 bottom
C23  106  [C0805]  92.88 142.67 0 bottom
C24  106  [C0805]  92.88 140.39 0 bottom
C25  104  [C0402]  80.21 137.24 270 bottom
C26  104  [C0402]  83.21 139.24 90 bottom
C27  104  [C0402]  80.21 139.24 270 bottom
C28  106  [C0805]  74.85 148.13 180 bottom
C29  106  [C0805]  97.2 144.96 0 bottom
C30  104  [C0402]  89.23 131.24 270 bottom
C31  104  [C0402]  88.21 131.22 90 bottom
C32  104  [C0402]  75.21 131.22 90 bottom
C33  104  [C0402]  74.21 131.22 270 bottom
C34  104  [C0402]  89.21 145.22 90 bottom
C35  104  [C0402]  88.21 145.22 270 bottom
C36  104  [C0402]  84.21 137.24 90 bottom
C37  104  [C0402]  84.21 139.24 90 bottom
C38  104  [C0402]  79.21 139.24 270 bottom
C39  104  [C0402]  75.21 145.22 270 bottom
C40  104  [C0402]  79.21 137.24 270 bottom
C41  104  [C0402]  74.21 145.22 90 bottom
C42  104  [C0402]  97.07 138.74 180 bottom
C43  104  [C0402]  75.36 159.56 180 bottom
C53  104  [C0402]  182.67 90.73 270 top
C54  104  [C0402]  167.56 94.41 270 bottom
C55  105  [C0402]  181.66 90.73 270 top
C56  10uF/6.3V  [C0402]  165.53 94.41 270 bottom
C57  10uF/6.3V  [C0402]  166.54 94.41 270 bottom
C58  103  [C0402]  173.53 104.98 0 top
C59  103  [C0402]  173.53 103.96 0 top
C60  103  [C0402]  177.29 104.45 270 top
C61  103  [C0402]  176.27 104.45 270 top
C62  0.1uF/25V  [C0402]  184.32 117.4 180 top
C63  0.1uF/25V  [C0402]  184.32 115.37 180 top
C64  0.1uF/25V  [C0402]  184.32 117.4 180 bottom
C65  0.1uF/25V  [C0402]  184.32 115.37 180 bottom
C66  1uF/25V  [C0402]  184.32 116.38 180 top
C67  1uF/25V  [C0402]  184.32 114.35 180 top
C68  1uF/25V  [C0402]  184.32 114.35 180 bottom
C69  12PF/50V  [C0402]  184.32 116.38 180 bottom
C70  4.7uF  [C0603]  33.83 27.86 270 top
C71  104  [C0603]  32.43 27.86 270 top
C72  104  [C0603]  26.46 27.81 90 top
C73  106  [C0805]  31.16 33.2 0 bottom
C74  106  [C0805]  31.16 30.91 0 bottom
C75  104  [C0603]  31.16 33.2 0 top
C76  102  [C0603]  35.1 32.44 0 top
C77  104  [C0603]  25.07 27.81 270 top
C78  22uF  [C0805]  23.03 31.55 270 bottom
C79  22uF  [C0805]  20.75 31.55 270 top
C80  106  [C0805]  20.75 31.55 270 bottom
C81  104  [C0603]  22.78 31.55 270 top
C82  10uF/25V  [C0805]  143.05 161.09 0 bottom
C83  10uF/25V  [C0805]  143.05 158.8 0 bottom
C84  104  [C0603]  142.54 161.6 0 top
C85  104  [C0603]  139.24 158.17 270 bottom
C86  X  [C0603]  133.78 159.44 180 bottom
C87  104  [C0402]  133.9 161.72 180 bottom
C88  105  [C0603]  133.78 155.25 0 bottom
C89  X  [C0603]  143.05 156.9 0 bottom
C90  103  [C0603]  133.78 153.85 0 bottom
C91  22uF/25V  [C0805]  147.87 155.25 180 bottom
C92  22uF/25V  [C0805]  147.87 159.82 180 bottom
C93  X  [C0805]  147.87 157.53 180 bottom
C94  104  [C0603]  148.13 162.1 180 top
C95  103  [C0603]  189.15 34.85 180 bottom
C96  105  [C0603]  189.15 39.04 0 bottom
C97  105  [C0603]  185.34 37.77 0 top
C98  220pF  [C0603]  189.15 36.25 180 bottom
C99  680pF  [C0603]  186.74 35.48 270 top
C100  103  [C0603]  189.15 37.64 180 bottom
C101  22uF/25V  [C0805]  196.39 32.44 90 bottom
C102  22uF/25V  [C0805]  200.2 33.71 180 top
C103  22uF/25V  [C0805]  200.2 35.99 180 top
C104  1uF/25V  [C0805]  198.67 32.44 90 bottom
C105  104  [C0603]  185.34 40.69 0 top
C106  22uF/25V  [C0805]  194.86 47.04 270 bottom
C107  22uF/25V  [C0805]  197.15 47.04 270 bottom
C108  22uF/25V  [C0805]  192.58 47.04 270 bottom
C109  22uF/25V  [C0805]  188.01 47.04 270 bottom
C110  22uF/25V  [C0805]  190.29 47.04 270 bottom
C111  104  [C0603]  184.7 50.47 180 top
C112  103  [C0603]  184.7 49.07 180 top
C113  102  [C0603]  200.2 38.02 180 top
C114  105  [C0603]  181.78 152.71 90 top
C115  105  [C0603]  182.8 154.99 0 bottom
C116  103  [C0603]  186.86 151.94 0 bottom
C117  220pF  [C0603]  185.97 152.71 90 top
C118  680pF  [C0603]  192.32 152.71 90 top
C119  103  [C0603]  184.58 152.71 270 bottom
C120  1uF/25V  [C0805]  191.05 161.09 180 bottom
C121  X  [C0805]  191.05 161.09 180 top
C122  10uF/25V  [C0805]  191.05 157.53 180 top
C123  10uF/25V  [C0805]  191.05 157.53 180 bottom
C124  104  [C0603]  180.51 156.01 270 bottom
C125  22uF  [C0805]  168.83 156.9 180 bottom
C126  22uF  [C0805]  168.83 159.18 180 bottom
C127  22uF  [C0805]  168.83 154.61 180 bottom
C128  X  [C0805]  168.83 161.47 180 bottom
C129  104  [C0603]  168.7 151.56 180 top
C130  103  [C0603]  168.7 153.09 180 top
C131  X  [C0603]  177.85 161.72 180 bottom
C132  180P  [C0402]  155.88 156.52 90 bottom
C133  22uF  [C0805]  152.45 154.86 180 bottom
C134  104  [C0603]  151.81 154.48 180 top
C135  10uF/10V  [C0805]  152.45 157.15 180 bottom
C136  22uF  [C0805]  152.45 152.58 180 bottom
C137  X  [C0603]  160.83 160.96 180 top
C138  104  [C0603]  165.15 153.09 0 bottom
C139  105  [C0603]  165.15 151.69 0 bottom
C140  104  [C0603]  165.15 151.69 180 top
C141  10uF/10V  [C0805]  159.05 157.02 180 bottom
C142  22uF  [C0805]  159.05 154.74 180 bottom
C143  10uF/25V  [C0805]  177.85 142.29 0 top
C144  10uF/25V  [C0805]  177.85 142.29 0 bottom
C145  104  [C0603]  173.15 143.05 180 top
C146  104  [C0603]  176.07 146.74 90 bottom
C147  X  [C0603]  184.96 146.86 180 top
C148  105  [C0603]  184.96 148.39 0 top
C149  X  [C0603]  175.56 149.15 0 bottom
C150  103  [C0603]  184.96 149.91 0 top
C151  22uF/25V  [C0805]  168.58 147.88 0 bottom
C152  22uF/25V  [C0805]  168.58 145.59 0 bottom
C153  X  [C0805]  168.58 143.18 0 bottom
C154  104  [C0603]  162.61 148.9 180 top
C155  10uF/25V  [C0805]  177.72 131.88 0 top
C156  10uF/25V  [C0805]  177.72 131.88 0 bottom
C157  104  [C0603]  173.02 132.51 180 top
C158  104  [C0603]  176.07 136.32 90 bottom
C159  X  [C0603]  184.32 136.96 180 top
C160  105  [C0603]  184.32 137.21 0 bottom
C161  X  [C0603]  172.77 139.5 0 bottom
C162  103  [C0603]  184.32 138.61 0 bottom
C163  22uF/25V  [C0805]  168.58 138.48 0 bottom
C164  22uF/25V  [C0805]  168.58 136.2 0 bottom
C165  X  [C0805]  168.83 133.78 0 bottom
C166  104  [C0603]  167.81 141.28 0 top
C167  180P  [C0402]  126.79 55.8 180 top
C168  104  [C0603]  129.97 55.93 0 top
C169  22uF  [C0805]  125.52 57.2 180 bottom
C170  22uF  [C0805]  125.52 59.49 180 bottom
C171  104  [C0603]  133.14 56.06 180 top
C172  10uF/10V  [C0805]  132 58.73 180 bottom
C173  22uF  [C0805]  132 61.01 180 bottom
C174  104  [C0603]  137.46 60.88 0 top
C175  X  [C0603]  137.46 59.49 0 top
C176  105  [C0603]  137.46 62.28 0 top
C177  22uF/25V  [C0805]  130.98 146.23 180 bottom
C178  104  [C0603]  136.32 146.99 90 top
C179  X  [C0402]  122.35 145.85 0 top
C180  104  [C0603]  122.47 148.51 180 top
C181  22uF/25V  [C0805]  127.94 148.77 0 bottom
C182  22uF/25V  [C0805]  90.22 122.1 180 bottom
C183  104  [C0603]  94.28 121.97 270 top
C184  X  [C0402]  85.9 116.89 180 top
C185  104  [C0603]  81.47 122.02 270 top
C186  22uF/25V  [C0805]  84.12 122.48 180 bottom
C187  10uF/25V  [C0805]  164.26 53.77 0 bottom
C188  10uF/25V  [C0805]  164.26 53.77 0 top
C189  104  [C0603]  164.26 51.74 0 top
C190  104  [C0603]  162.99 58.47 90 bottom
C191  X  [C0603]  171.37 64.44 270 bottom
C192  105  [C0603]  172.77 64.44 90 bottom
C193  X  [C0603]  161.46 61.52 0 bottom
C194  103  [C0603]  168.96 64.82 180 bottom
C195  22uF/25V  [C0805]  155.37 61.52 0 bottom
C196  22uF/25V  [C0805]  155.37 54.79 0 bottom
C197  104  [C0603]  150.29 62.28 180 top
C198  47uF/6.3V  [C0805]  155.37 59.23 0 bottom
C199  X  [C0603]  142.29 61.39 180 bottom
C200  47uF/6.3V  [C0805]  138.35 55.17 180 bottom
C201  47uF/6.3V  [C0805]  138.35 57.46 180 bottom
C202  105  [C0603]  138.35 53.65 180 top
C203  105  [C0603]  141.65 53.52 0 top
C204  105  [C0603]  138.35 56.44 180 top
C205  104  [C0603]  138.35 55.04 180 top
C206  105  [C0603]  138.35 57.96 180 top
C207  104  [C0603]  150.29 54.79 0 top
C208  10uF/10V  [C0805]  145.72 57.96 180 bottom
C209  22uF  [C0805]  145.72 55.68 180 bottom
C210  104  [C0603]  150.29 56.19 0 top
C211  105  [C0603]  150.29 57.58 0 top
C212  10uF/25V  [C0805]  160.32 63.81 180 bottom
C213  10uF/25V  [C0805]  160.32 66.09 180 bottom
C214  104  [C0603]  166.42 64.06 0 top
C215  104  [C0603]  164.64 68.12 90 bottom
C216  X  [C0603]  173.53 67.23 180 top
C217  X  [C0603]  165.15 72.44 0 top
C218  105  [C0603]  170.35 69.01 180 bottom
C219  X  [C0603]  170.35 71.81 180 bottom
C220  103  [C0603]  170.35 70.41 180 bottom
C221  22uF/25V  [C0805]  155.37 66.09 0 bottom
C222  22uF/25V  [C0805]  155.37 63.81 0 bottom
C223  104  [C0603]  155.11 71.55 0 top
C224  105  [C0402]  166.44 15.16 90 top
C225  105  [C0402]  162.12 14.15 90 top
C226  10uF/6.3V  [C0402]  148.64 22.66 180 bottom
C227  10uF/6.3V  [C0402]  148.64 23.67 180 bottom
C228  104  [C0402]  123.62 76.38 90 top
C229  104  [C0402]  136.7 102.16 180 bottom
C230  104  [C0402]  61.01 13.89 270 top
C231  105  [C0402]  107.74 46.28 0 top
C232  105  [C0402]  124.13 40.95 180 top
C233  105  [C0402]  124 45.01 90 top
C234  105  [C0402]  31.42 87.68 90 bottom
C235  105  [C0402]  4.36 49.45 90 bottom
C236  105  [C0402]  113.71 97.59 0 top
C237  1uF/25V  [C0402]  161.34 142.93 270 bottom
C238  104  [C0402]  151.05 145.47 90 bottom
C239  1uF/25V  [C0402]  157.65 144.96 180 bottom
C240  1uF/25V  [C0402]  147.75 135.81 270 bottom
C241  1uF/25V  [C0402]  151.18 136.58 270 bottom
C242  1uF/25V  [C0402]  148.26 145.47 90 bottom
C243  1uF/25V  [C0402]  153.84 136.96 90 bottom
C244  104  [C0402]  151.05 123.5 180 bottom
C245  0.22uF/10V  [C0402]  154.48 140.01 270 bottom
C246  104  [C0402]  159.81 144.96 180 bottom
C247  104  [C0402]  148.89 135.81 90 bottom
C248  1uF/25V  [C0402]  155.49 135.81 270 bottom
C249  4.7uF/6.3V  [C0402]  154.1 143.56 90 bottom
C250  1uF/25V  [C0402]  159.43 136.2 180 bottom
C251  100P  [C0402]  159.18 141.91 180 bottom
C252  103  [C0402]  141.78 146.48 180 top
C253  105  [C0402]  141.78 147.5 180 top
C254  104  [C0402]  137.46 134.93 0 bottom
C255  104  [C0402]  137.46 135.94 0 bottom
C256  104  [C0402]  92.07 89.08 270 bottom
C257  104  [C0402]  101.9 139.37 180 top
C258  30pf/50V  [C0402]  149.02 105.84 270 top
C259  104  [C0402]  150.92 111.58 180 bottom
C260  4.7uF/6.3V  [C0402]  150.92 110.57 0 bottom
C261  104  [C0402]  143.68 129.08 180 bottom
C262  104  [C0402]  139.24 137.47 0 top
C263  104  [C0402]  164.77 111.68 180 top
C264  104  [C0402]  164.77 112.7 180 top
C265  104  [C0402]  165.15 89.08 0 top
C266  106  [C0805]  178.99 112.98 90 top
C267  106  [C0805]  176.45 112.98 90 top
C268  104  [C0402]  165.53 117.27 90 top
C269  104  [C0402]  173.27 110.16 180 top
C270  104  [C0402]  169.21 109.65 0 top
C271  104  [C0402]  168.83 118.54 180 top
C272  106  [C0805]  166.42 122.61 270 top
C273  106  [C0805]  177.72 129.21 180 bottom
C274  104  [C0402]  168.83 117.53 0 top
C275  104  [C0402]  173.66 117.65 270 top
C276  104  [C0402]  173.66 115.37 90 top
C277  104  [C0402]  172.64 117.65 270 top
C278  106  [C0805]  161.72 122.99 0 bottom
C279  106  [C0805]  170.99 129.85 0 bottom
C280  27P  [C0402]  172 122.99 0 top
C281  27P  [C0402]  169.85 122.99 180 top
C282  106  [C0805]  161.72 127.56 0 bottom
C283  106  [C0805]  161.72 125.27 0 bottom
C284  104  [C0402]  164.51 117.27 270 top
C285  104  [C0402]  173.66 113.21 90 top
C286  104  [C0402]  170.99 118.54 0 top
C287  104  [C0402]  167.05 109.65 180 top
C288  39nF/16V  [C0402]  166.92 123.37 0 bottom
C289  X  [C0402]  166.92 124.38 0 bottom
C290  105  [C0402]  153.46 120.96 0 bottom
C291  105  [C0402]  153.46 122.61 0 bottom
C292  104  [C0402]  160.83 112.24 0 bottom
C293  104  [C0402]  161.21 113.59 180 top
C294  104  [C0402]  145.59 122.23 270 bottom
C295  105  [C0402]  141.52 117.15 180 bottom
C296  104  [C0402]  161.21 112.29 0 top
C297  105  [C0402]  147.49 124.26 90 bottom
C298  104  [C0402]  154.35 116.97 0 bottom
C299  105  [C0402]  148.64 122.23 270 bottom
C300  105  [C0402]  150.29 122.48 0 bottom
C301  105  [C0402]  146.6 122.23 270 bottom
C302  105  [C0402]  143.94 120.96 0 bottom
C303  105  [C0402]  147.49 114.48 90 bottom
C304  105  [C0402]  142.29 115.11 180 bottom
C305  4.7uF/6.3V  [C0402]  157.53 118.54 90 bottom
C306  100P  [C0402]  154.35 117.98 0 bottom
C307  104  [C0402]  161.21 107.21 0 top
C308  105  [C0402]  150.29 118.29 180 bottom
C309  105  [C0402]  150.54 120.83 270 bottom
C310  105  [C0402]  147.49 116.13 180 bottom
C311  105  [C0402]  145.46 116.13 180 bottom
C312  105  [C0402]  143.94 121.97 0 bottom
C313  105  [C0402]  144.19 117.4 90 bottom
C314  4.7uF/6.3V  [C0402]  142.54 119.43 180 bottom
C315  10uf/6.3V  [C0603]  147.49 119.56 270 bottom
C316  105  [C0402]  152.65 116.21 0 bottom
C317  100P  [C0402]  157.53 114.35 90 bottom
C318  105  [C0402]  141.52 116.13 180 bottom
C319  104  [C0402]  144.19 119.43 90 bottom
C320  105  [C0402]  151.3 119.3 180 bottom
C321  104  [C0402]  157.53 120.7 270 bottom
C322  100P  [C0402]  153.34 119.3 0 bottom
C323  105  [C0402]  142.06 126.95 90 bottom
C324  104  [C0402]  142.29 125.15 180 bottom
C325  100P  [C0402]  147.62 122.23 270 bottom
C326  105  [C0402]  150.29 117.15 180 bottom
C327  104  [C0402]  157.53 116.43 90 bottom
C328  100P  [C0402]  149.53 116.13 180 bottom
C335  105  [C0402]  117.01 25.45 0 top
C336  102  [C0402]  127.43 19.86 0 bottom
C337  1uF/25V  [C0805]  117.65 12.42 270 top
C338  2200pF  [C0603]  120.82 15.93 90 top
C339  104  [C0402]  117.47 19.61 180 top
C340  105  [C0402]  123.11 16.31 270 top
C341  104  [C0402]  66.34 16.82 0 bottom
C342  22uF/25V  [C0805]  110.54 12.75 0 bottom
C343  22uF/25V  [C0805]  110.54 15.04 0 bottom
C344  10uF/25V  [C0805]  106.6 16.56 90 bottom
C345  4700pF  [C0603]  107.11 16.43 90 top
C346  104  [C0402]  112.06 13.26 270 top
C347  2200pF  [C0603]  104.06 19.23 180 top
C348  47uF/6.3V  [C0805]  105.84 30.79 270 bottom
C349  47uF/6.3V  [C0805]  103.3 48.44 90 top
C350  47uF/6.3V  [C0805]  114.47 36.63 0 top
C351  47uF/6.3V  [C0805]  93.01 39.68 180 top
C352  47uF/6.3V  [C0805]  103.3 48.44 90 bottom
C353  47uF/6.3V  [C0805]  114.47 36.63 0 bottom
C354  47uF/6.3V  [C0805]  114.47 34.34 0 bottom
C355  47uF/6.3V  [C0805]  114.47 34.34 0 top
C356  47uF/6.3V  [C0805]  93.01 41.96 180 bottom
C357  2.2uF/25V  [C0603]  114.22 24.31 90 bottom
C358  102  [C0402]  115.11 15.42 90 top
C359  47uF/6.3V  [C0805]  92.38 47.68 270 top
C360  47uF/6.3V  [C0805]  114.47 32.06 0 bottom
C361  47uF/6.3V  [C0805]  114.47 32.06 0 top
C362  47uF/6.3V  [C0805]  114.47 29.77 0 bottom
C363  47uF/6.3V  [C0805]  103.17 30.79 270 top
C364  47uF/6.3V  [C0805]  93.01 41.96 180 top
C365  47uF/6.3V  [C0805]  105.58 48.44 90 top
C366  47uF/6.3V  [C0805]  101.01 48.44 90 bottom
C367  47uF/6.3V  [C0805]  105.58 48.44 90 bottom
C368  22uF  [C0805]  93.01 39.68 180 bottom
C369  104  [C0402]  116 21.01 0 top
C370  22uF/25V  [C0805]  98.6 12.75 0 bottom
C371  22uF/25V  [C0805]  98.6 15.04 0 bottom
C372  10uF/25V  [C0805]  94.66 16.56 90 bottom
C373  4700pF  [C0603]  95.17 16.43 90 top
C374  104  [C0402]  100.63 13.26 270 top
C375  2200pF  [C0603]  91.99 19.99 180 top
C376  47uF/6.3V  [C0805]  90.09 47.68 270 top
C377  47uF/6.3V  [C0805]  93.01 37.39 180 top
C378  47uF/6.3V  [C0805]  107.23 37.9 0 top
C379  47uF/6.3V  [C0805]  98.73 48.44 90 top
C380  47uF/6.3V  [C0805]  92.63 32.82 180 bottom
C381  47uF/6.3V  [C0805]  107.23 40.18 0 bottom
C382  47uF/6.3V  [C0805]  92.63 35.1 180 bottom
C383  47uF/6.3V  [C0805]  101.27 30.79 270 bottom
C384  47uF/6.3V  [C0805]  107.23 42.47 0 top
C385  2.2uF/25V  [C0603]  102.79 23.42 90 bottom
C386  102  [C0402]  103.17 15.67 90 top
C387  47uF/6.3V  [C0805]  107.23 42.47 0 bottom
C388  47uF/6.3V  [C0805]  107.87 48.44 90 bottom
C389  47uF/6.3V  [C0805]  107.23 40.18 0 top
C390  47uF/6.3V  [C0805]  103.55 30.79 270 bottom
C391  47uF/6.3V  [C0805]  93.01 44.25 180 bottom
C392  47uF/6.3V  [C0805]  107.23 37.9 0 bottom
C393  47uF/6.3V  [C0805]  114.47 27.48 0 bottom
C394  47uF/6.3V  [C0805]  93.01 44.25 180 top
C395  47uF/6.3V  [C0805]  101.01 48.44 90 top
C396  22uF  [C0805]  93.01 37.39 180 bottom
C397  104  [C0402]  104.06 20.75 0 top
C398  22uF/25V  [C0805]  127.17 7.42 90 bottom
C399  22uF/25V  [C0805]  129.46 7.42 90 bottom
C400  22uF/25V  [C0805]  95.68 7.04 270 bottom
C401  22uF/25V  [C0805]  106.6 7.04 270 bottom
C402  2200pF  [C0603]  127.17 17.3 180 top
C403  100uF/6.3V  [C1206]  135.81 31.29 270 bottom
C404  47uF/6.3V  [C0805]  127.81 30.53 270 top
C405  47uF/6.3V  [C0805]  126.67 38.18 90 top
C406  47uF/6.3V  [C0805]  131.24 38.18 90 top
C407  47uF/6.3V  [C0805]  120.95 37.14 180 bottom
C408  4700pF  [C0603]  129.59 13.39 180 top
C409  22uF/25V  [C0805]  129.59 14.53 180 bottom
C410  22uF/25V  [C0805]  129.59 11.35 180 bottom
C411  10uF/25V  [C0805]  129.46 11.35 180 top
C412  22uF  [C0805]  128.95 38.18 90 bottom
C413  22uF  [C0805]  127.81 30.53 270 bottom
C414  22uF  [C0805]  131.24 38.18 90 bottom
C415  22uF  [C0805]  128.95 38.18 90 top
C416  22uF  [C0805]  125.52 30.53 270 bottom
C417  22uF  [C0805]  123.24 30.53 270 bottom
C418  22uF  [C0805]  126.67 38.18 90 bottom
C419  22uF  [C0805]  120.95 34.85 180 bottom
C420  22uF  [C0805]  123.24 30.53 270 top
C421  2.2uF  [C0805]  125.52 30.53 270 top
C422  104  [C0402]  133.4 13.77 90 bottom
C423  2.2uF/25V  [C0603]  136.83 17.73 270 bottom
C424  104  [C0402]  136.19 19.36 270 top
C425  102  [C0402]  136.44 16.18 90 top
C426  105  [C0402]  162.99 39.29 180 top
C427  102  [C0402]  174.29 34.47 0 top
C428  1uF/25V  [C0805]  164.89 26.59 270 top
C429  2200pF  [C0603]  168.07 29.52 90 top
C430  104  [C0402]  162.99 34.98 180 top
C431  105  [C0402]  170.48 29.9 270 top
C432  2200pF  [C0603]  151.05 37.14 270 top
C433  100uF/6.3V  [C1206]  142.92 37.52 0 bottom
C434  47uF/6.3V  [C0805]  128.19 44.25 90 top
C435  47uF/6.3V  [C0805]  133.52 38.66 270 bottom
C436  47uF/6.3V  [C0805]  135.05 44.25 90 top
C437  47uF/6.3V  [C0805]  142.41 35.1 0 bottom
C438  47uF/6.3V  [C0805]  132.76 44.25 90 bottom
C439  47uF/6.3V  [C0805]  128.19 44.25 90 bottom
C440  47uF/6.3V  [C0805]  137.33 44.25 90 top
C441  22uF/25V  [C0805]  159.56 35.23 0 bottom
C442  22uF/25V  [C0805]  160.32 37.01 270 top
C443  10uF/25V  [C0805]  159.56 32.69 0 bottom
C444  4700pF  [C0603]  158.44 37.01 270 top
C445  22uF  [C0805]  132.76 44.25 90 top
C446  22uF  [C0805]  135.05 44.25 90 bottom
C447  22uF  [C0805]  130.48 44.25 90 top
C448  22uF  [C0805]  130.48 44.25 90 bottom
C449  22uF  [C0805]  135.81 38.66 270 bottom
C450  22uF  [C0805]  125.9 44.25 90 bottom
C451  104  [C0402]  159.3 41.2 180 top
C452  2.2uF/25V  [C0603]  153.97 35.99 0 bottom
C453  104  [C0402]  153.46 44.2 0 top
C454  102  [C0402]  157.15 43.87 180 top
C455  2200pF  [C0603]  151.43 46.15 270 top
C456  100uF/6.3V  [C1206]  140.76 51.99 0 bottom
C457  47uF/6.3V  [C0805]  131.24 48.69 270 top
C458  47uF/6.3V  [C0805]  131.24 48.69 270 bottom
C459  47uF/6.3V  [C0805]  133.52 48.69 270 bottom
C460  22uF/25V  [C0805]  159.94 47.3 0 bottom
C461  22uF/25V  [C0805]  160.83 46.66 270 top
C462  4700pF  [C0603]  158.92 46.91 270 top
C463  10uF/25V  [C0805]  159.94 49.58 0 bottom
C464  10uf/6.3V  [C0603]  130.98 53.65 90 top
C465  22uF  [C0805]  133.52 48.69 270 top
C466  22uF  [C0805]  135.81 48.69 270 top
C467  22uF  [C0805]  135.81 48.69 270 bottom
C468  22uF  [C0805]  128.95 48.69 270 bottom
C469  22uF  [C0805]  111.55 78.54 0 bottom
C470  22uF  [C0805]  111.55 80.82 0 bottom
C471  104  [C0402]  161.34 50.98 180 top
C472  2.2uF/25V  [C0603]  149.78 52.89 180 bottom
C473  104  [C0402]  150.41 53.39 180 top
C474  102  [C0402]  157.02 53.14 180 top
C475  22uF/25V  [C0805]  174.67 48.44 0 top
C476  22uF/25V  [C0805]  174.67 46.15 0 top
C477  22uF/25V  [C0805]  155.49 45.01 180 bottom
C478  105  [C0402]  56.05 24.94 180 top
C479  102  [C0402]  66.34 20.88 0 top
C480  1uF/25V  [C0805]  55.8 14.53 180 top
C481  2200pF  [C0603]  59.74 15.93 90 top
C482  104  [C0402]  55.67 21.39 180 top
C483  105  [C0402]  62.05 16.31 270 top
C484  22uF/25V  [C0805]  86.53 12.75 0 bottom
C485  22uF/25V  [C0805]  86.53 15.04 0 bottom
C486  10uF/25V  [C0805]  82.6 16.56 90 bottom
C487  4700pF  [C0603]  83.1 16.43 90 top
C488  2200pF  [C0603]  79.93 19.36 180 top
C489  104  [C0402]  88.06 13.26 270 top
C490  100uF/6.3V  [C1206]  86.03 39.04 0 top
C491  22uF  [C0805]  85.52 49.2 90 top
C492  22uF  [C0805]  85.77 43.99 0 bottom
C493  22uF  [C0805]  85.77 41.71 0 bottom
C494  22uF  [C0805]  78.91 34.85 180 top
C495  22uF  [C0805]  85.77 41.71 0 top
C496  2.2uF/25V  [C0603]  90.47 23.8 90 bottom
C497  102  [C0402]  91.11 15.93 90 top
C498  104  [C0402]  91.87 21.26 0 top
C499  2200pF  [C0603]  70.54 25.07 270 top
C500  47uF/6.3V  [C0805]  59.61 39.93 90 bottom
C501  47uF/6.3V  [C0805]  57.32 39.93 90 bottom
C502  22uF  [C0805]  63.55 31.29 270 top
C503  22uF  [C0805]  76.37 30.91 270 bottom
C504  22uF  [C0805]  61.26 31.29 270 top
C506  105  [C0402]  67.61 30.66 270 top
C507  22uF/25V  [C0805]  71.67 16.69 90 top
C508  22uF/25V  [C0805]  69.39 16.69 90 top
C509  4700pF  [C0603]  71.67 16.69 90 bottom
C510  10uF/25V  [C0805]  69.39 16.69 90 bottom
C511  104  [C0402]  75.87 13.77 90 top
C512  2.2uF/25V  [C0603]  78.67 23.04 90 bottom
C513  104  [C0402]  79.8 20.63 0 top
C514  102  [C0402]  78.91 16.05 90 top
C515  22uF/25V  [C0805]  80.18 5.89 0 bottom
C516  22uF/25V  [C0805]  80.18 3.61 0 bottom
C517  22uF/25V  [C0805]  84.5 7.04 270 bottom
C518  22UF  [C0603]  15.41 70.79 270 bottom
C519  22UF  [C0603]  4.49 70.79 270 bottom
C520  22UF  [C0603]  7.03 70.79 270 bottom
C521  22UF  [C0603]  22.02 70.79 270 bottom
C524  10uf/6.3V  [C0603]  2.84 49.71 90 bottom
C527  10uf/6.3V  [C0603]  9.44 44.63 270 bottom
C528  103  [C0402]  23.8 70.66 270 bottom
C550  103  [C0402]  11.95 70.16 270 bottom
C562  105  [C0402]  102.41 129.72 180 top
C563  103  [C0402]  125.4 143.82 180 bottom
C564  104  [C0402]  107.74 129.46 180 bottom
C565  105  [C0402]  119.3 141.02 180 top
C566  103  [C0402]  119.3 139.5 180 top
C567  104  [C0402]  101.9 142.42 0 top
C568  104  [C0402]  113.84 87.3 180 top
C569  104  [C0402]  113.84 88.32 180 top
C570  0.1uF/25V  [C0402]  183.56 83.62 0 bottom
C571  0.1uF/25V  [C0402]  183.56 82.6 0 bottom
C572  0.1uF/25V  [C0402]  183.56 80.57 0 bottom
C573  0.1uF/25V  [C0402]  183.56 81.59 0 bottom
C574  0.1uF/25V  [C0402]  183.56 87.68 0 bottom
C575  0.1uF/25V  [C0402]  183.56 86.67 0 bottom
C576  0.1uF/25V  [C0402]  183.56 85.65 0 bottom
C577  0.1uF/25V  [C0402]  183.56 84.63 0 bottom
C578  104  [C0402]  108.89 66.73 180 bottom
C579  104  [C0402]  108.89 65.71 180 bottom
C580  104  [C0402]  108.89 68.76 180 bottom
C581  104  [C0402]  108.89 67.74 180 bottom
C582  27P  [C0402]  116.12 67.87 270 top
C583  27P  [C0402]  116.12 70.03 90 top
C584  104  [C0402]  113.97 86.03 0 bottom
C585  104  [C0402]  113.97 87.05 0 bottom
C586  10pf/50V  [C0201]  114.09 70.92 180 bottom
C587  18pF  [C0603]  99.23 107.11 0 top
C588  18pF  [C0603]  96.06 107.11 180 top
C589  27P  [C0402]  107.23 105.21 270 top
C590  27P  [C0402]  108.76 105.21 270 top
C591  104  [C0603]  125.52 122.1 180 bottom
C592  106  [C0805]  125.52 126.29 180 bottom
C593  104  [C0603]  125.4 128.19 0 bottom
C594  103  [C0402]  61.77 67.11 90 bottom
C595  104  [C0402]  99.49 117.4 0 top
C596  104  [C0402]  88.82 91.62 180 bottom
C597  105  [C0402]  90.09 88.95 180 bottom
C598  105  [C0402]  90.09 89.97 180 bottom
C599  105  [C0402]  95.93 94.29 180 bottom
C600  105  [C0402]  93.11 83.49 180 bottom
C601  105  [C0402]  90.09 87.94 180 bottom
C602  X  [C0402]  82.34 97.21 90 bottom
C603  104  [C0603]  108.38 84.25 270 bottom
C604  103  [C0603]  106.98 84.25 270 bottom
C605  105  [C0402]  112.95 62.79 0 bottom
C606  47uF/6.3V  [C0805]  112.95 61.14 0 bottom
C607  105  [C0402]  104.44 78.92 0 bottom
C608  47uF/6.3V  [C0805]  114.75 77.14 0 top
C613  104  [C0402]  73.07 125.65 90 top
C614  104  [C0402]  101.52 59.99 270 bottom
C615  22uF/6.3V  [C0603]  87.3 70.42 180 bottom
C616  22uF/6.3V  [C0603]  87.3 71.97 180 bottom
C617  22uF/6.3V  [C0603]  87.3 79.69 180 bottom
C618  22uF/6.3V  [C0603]  87.3 78.17 180 bottom
C619  22uF/6.3V  [C0603]  90.6 78.91 0 bottom
C620  22uF/6.3V  [C0603]  90.6 80.43 0 bottom
C621  22uF/6.3V  [C0603]  86.15 63.31 180 bottom
C622  22uF/6.3V  [C0603]  90.6 72.81 0 bottom
C623  22uF/6.3V  [C0603]  95.3 77.15 180 bottom
C624  22uF/6.3V  [C0603]  87.3 76.64 180 bottom
C625  22uF/6.3V  [C0603]  95.3 75.5 180 bottom
C626  22uF/6.3V  [C0603]  87.3 73.64 180 bottom
C627  22uF/6.3V  [C0603]  90.6 75.86 0 bottom
C628  22uF/6.3V  [C0603]  87.3 75.14 180 bottom
C629  22uF/6.3V  [C0603]  90.6 77.38 0 bottom
C630  22uF/6.3V  [C0603]  90.6 74.33 0 bottom
C631  22uF/6.3V  [C0603]  103.42 75.87 0 bottom
C632  22uF/6.3V  [C0603]  98.6 76.76 180 bottom
C633  2.2uf/10V  [C0402]  102.28 77.14 0 bottom
C634  47uF/6.3V  [C0805]  116.25 74.98 90 bottom
C635  105  [C0402]  100.55 73.76 0 bottom
C636  105  [C0402]  99.11 75.24 180 bottom
C637  105  [C0402]  102.15 74.63 0 bottom
C638  22uF/6.3V  [C0603]  101.01 71.43 180 bottom
C639  47uF/6.3V  [C0805]  111.68 76.25 0 bottom
C640  47uF/6.3V  [C0805]  111.68 73.97 0 bottom
C641  22uF/6.3V  [C0603]  97.07 73.74 0 bottom
C642  105  [C0402]  93.77 71.93 270 bottom
C643  105  [C0402]  93.14 75.11 90 bottom
C644  105  [C0402]  93.77 91.87 90 bottom
C645  104  [C0402]  91.11 84.63 180 bottom
C646  104  [C0402]  90.47 86.13 270 bottom
C647  104  [C0402]  92.86 85.06 90 bottom
C648  104  [C0402]  91.87 92.13 180 bottom
C649  105  [C0402]  94.79 71.93 270 bottom
C650  105  [C0402]  95.3 92.76 0 bottom
C651  105  [C0402]  98.98 88.82 0 bottom
C652  105  [C0402]  97.71 93.14 90 bottom
C653  105  [C0402]  98.62 91.67 0 bottom
